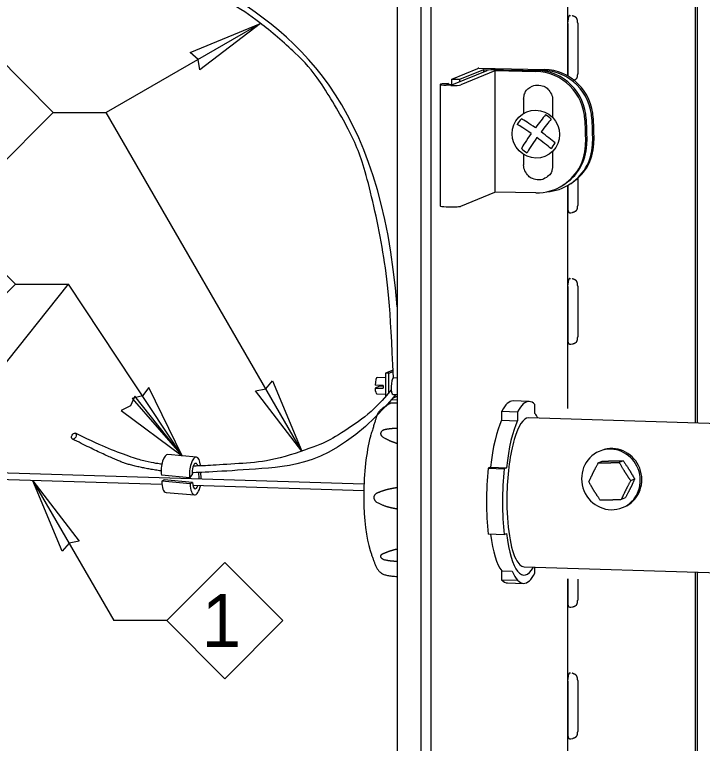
# Model space of a CAD drawing. Extents: x 99862 to 104211, y 98939 to 102076.
# Drawn here: x 102537.9 to 102745.8, y 100948.7 to 101168.9 of the extents above; entities that cross this region are included whole.
import ezdxf

# ---------------------------------------------------------------- set-up
doc = ezdxf.new("R2010")
doc.units = 0
for name, color, linetype in [('Level 1', 7, 'Continuous'), ('Level 11', 7, 'Continuous'), ('Level 15', 7, 'Continuous'), ('Level 16', 7, 'Continuous'), ('Level 18', 7, 'Continuous'), ('Level 19', 7, 'Continuous'), ('Level 20', 7, 'Continuous'), ('Level 22', 7, 'Continuous'), ('Level 30', 7, 'Continuous'), ('Level 4', 7, 'Continuous'), ('Level 5', 7, 'Continuous'), ('Level 6', 7, 'Continuous'), ('Level 8', 7, 'Continuous'), ('Level 9', 7, 'Continuous')]:
    doc.layers.add(name, color=color, linetype=linetype)

msp = doc.modelspace()

# ---------------------------------------------------------------- linework, layer by layer
at = {"layer": 'Level 1'}
for p, q in [((102705.04, 101245.44), (102705.04, 101150.38)), ((102660.74, 101228.18), (102660.74, 100794.54)), ((102663.81, 100794.74), (102663.81, 101228.38)), ((102653.5, 101220.95), (102653.5, 100802.46)), ((102705.04, 101117.28), (102705.04, 101049.91)), ((102705.13, 101049.91), (102705.13, 101070.65)), ((102705.04, 100998.38), (102705.04, 100905.03))]:
    msp.add_line(p, q, dxfattribs=at)
at = {"layer": 'Level 11'}
msp.add_ellipse((102695.46, 101132.81), major_axis=(-4.03, 6.06), ratio=0.979824, dxfattribs=at)
for centre, major_axis, ratio, start_param, end_param in [((102695.55, 101132.92), (-5.39, -3.58), 0.979824, 4.901469, 5.233429), ((102696.66, 101133.08), (6.17, -4.54), 0.069723, 1.843795, 2.744743), ((102695.44, 101134.01), (4.54, 6.17), 0.069723, 0.774623, 1.506857), ((102697.16, 101132.74), (-4.54, -6.17), 0.069723, 3.916018, 4.645885), ((102695.6, 101132.9), (3.58, -5.39), 0.979824, 1.762443, 2.094403), ((102695.39, 101131.36), (-6.17, 4.54), 0.069723, 4.983765, 5.886534), ((102695.44, 101134.01), (4.54, 6.17), 0.069723, 1.787106, 2.744743), ((102696.66, 101133.08), (6.17, -4.54), 0.069723, 0.774623, 1.561852), ((102697.16, 101132.74), (-4.54, -6.17), 0.069723, 4.926025, 5.886534), ((102695.39, 101131.36), (-6.17, 4.54), 0.069723, 3.916018, 4.702017), ((102695.55, 101132.92), (-5.39, -3.58), 0.979824, 1.762443, 2.094403), ((102695.6, 101132.9), (3.58, -5.39), 0.979824, 4.901469, 5.233429)]:
    msp.add_ellipse(centre, major_axis=major_axis, ratio=ratio, start_param=start_param, end_param=end_param, dxfattribs=at)
at = {"layer": 'Level 15'}
for p, q in [((102612.19, 101166.29), (102565.57, 101139.38)), ((102549.57, 101139.38), (102565.57, 101139.38)), ((102624.71, 101036.95), (102565.57, 101139.38)), ((102514.53, 101037.79), (102554.21, 101087.44)), ((102538.21, 101087.44), (102554.21, 101087.44)), ((102588.56, 101035.57), (102554.21, 101087.44)), ((102543.46, 101028.07), (102567.88, 100985.78)), ((102583.88, 100985.78), (102567.88, 100985.78))]:
    msp.add_line(p, q, dxfattribs=at)
for points in [[(102612.19, 101166.29), (102593.92, 101152.29), (102593.34, 101155.41), (102590.93, 101157.46)], [(102624.71, 101036.95), (102610.71, 101055.23), (102613.82, 101055.81), (102615.88, 101058.22)], [(102588.56, 101035.57), (102578.44, 101056.25), (102576.54, 101053.72), (102573.46, 101052.96)], [(102588.56, 101035.57), (102574.25, 101053.61), (102572.93, 101050.73), (102570.09, 101049.32)], [(102543.46, 101028.07), (102557.46, 101009.79), (102554.35, 101009.21), (102552.29, 101006.8)]]:
    msp.add_lwpolyline(points, close=True, dxfattribs=at)
at = {"layer": 'Level 16'}
for p, q in [((102592.85, 101035.17), (102584.26, 101035.97)), ((102594.12, 101032.54), (102594.1, 101032.72)), ((102590.86, 101028.94), (102582.27, 101029.73)), ((102590.86, 101028.94), (102591.58, 101029.85)), ((102593.46, 101030.52), (102593.57, 101028.75)), ((102594.34, 101028.79), (102594.23, 101030.54)), ((102583.13, 101028.31), (102582.38, 101027.94)), ((102590.96, 101027.15), (102582.38, 101027.94)), ((102591.72, 101027.52), (102583.13, 101028.31)), ((102591.72, 101027.52), (102590.96, 101027.15)), ((102583.68, 101024.55), (102592.26, 101023.76))]:
    msp.add_line(p, q, dxfattribs=at)
for centre, major_axis, start_param, end_param in [((102583.88, 101031.76), (0.39, 4.21), 0, 2.107327), ((102592.46, 101030.96), (0.39, 4.21), 0, 2.107327), ((102592.46, 101030.96), (0.39, 4.21), 5.178942, 6.283185), ((102592.46, 101030.96), (-0.21, -2.33), 3.141593, 5.248919), ((102592.46, 101030.96), (-0.21, -2.33), 2.333431, 3.141593), ((102592.65, 101027.97), (-0.21, -2.33), 1.854796, 1.949891), ((102592.65, 101027.97), (0.39, 4.21), 4.8789, 4.944488), ((102584.06, 101028.76), (0.39, 4.21), 1.802895, 3.141593), ((102592.65, 101027.97), (0.39, 4.21), 1.802895, 3.141593), ((102592.65, 101027.97), (-0.21, -2.33), 4.944488, 6.283185), ((102592.65, 101027.97), (0.39, 4.21), 3.141593, 4.398099), ((102592.65, 101027.97), (-0.21, -2.33), 0, 0.950425)]:
    msp.add_ellipse(centre, major_axis=major_axis, ratio=0.389923, start_param=start_param, end_param=end_param, dxfattribs=at)
at = {"layer": 'Level 18'}
for p, q in [((102744.31, 101045.46), (102744.31, 101252.37)), ((102743.65, 101000.46), (102743.65, 100805.07))]:
    msp.add_line(p, q, dxfattribs=at)
for points in [[(102685.75, 101253.86), (102686.4, 101254.13), (102744.31, 101252.37), (102743.65, 101252.1), (102743.65, 101045.48)], [(102696.2, 100806.51), (102743.65, 100805.07), (102744.31, 100805.34), (102744.31, 101000.44)]]:
    msp.add_lwpolyline(points, dxfattribs=at)
at = {"layer": 'Level 19'}
for p, q in [((102715.12, 101037.13), (102714.63, 101036.93)), ((102714.32, 101033.44), (102715.54, 101033.94)), ((102721.86, 101034.12), (102720.63, 101033.61)), ((102725.32, 101028.57), (102724.1, 101028.06)), ((102722.47, 101022.84), (102721.25, 101022.34)), ((102721.66, 101019.94), (102722.15, 101020.14))]:
    msp.add_line(p, q, dxfattribs=at)
for centre, start_param, end_param in [((102718.15, 101028.44), 2.914664, 3.141593), ((102718.63, 101028.64), 2.914664, 3.141593), ((102718.15, 101028.44), 6.283185, 9.197849), ((102718.63, 101028.64), 6.283185, 9.197849), ((102718.15, 101028.44), 3.141593, 6.283185)]:
    msp.add_ellipse(centre, major_axis=(3.52, -8.5), ratio=0.959029, start_param=start_param, end_param=end_param, dxfattribs=at)
for points in [[(102711.47, 101027.71), (102712.34, 101029.59), (102713.28, 101031.49), (102714.32, 101033.44)], [(102714.32, 101033.44), (102716.34, 101033.46), (102718.44, 101033.52), (102720.63, 101033.61)], [(102715.54, 101033.94), (102717.73, 101034.04), (102719.84, 101034.1), (102721.86, 101034.12)], [(102720.63, 101033.61), (102721.96, 101031.32), (102723, 101029.68), (102724.1, 101028.06)], [(102721.86, 101034.12), (102723.35, 101031.9), (102724.37, 101030.25), (102725.32, 101028.57)], [(102725.32, 101028.57), (102724.46, 101026.7), (102723.51, 101024.79), (102722.47, 101022.84)], [(102714.94, 101022.16), (102713.69, 101023.97), (102712.55, 101025.83), (102711.47, 101027.71)], [(102724.1, 101028.06), (102723.07, 101026.12), (102722.11, 101024.21), (102721.25, 101022.34)], [(102721.25, 101022.34), (102719.06, 101022.24), (102716.96, 101022.18), (102714.94, 101022.16)]]:
    msp.add_open_spline(points, degree=2, dxfattribs=at)
at = {"layer": 'Level 20'}
for points in [[(102532.02, 101156.93), (102549.57, 101139.38), (102532.02, 101121.82), (102514.47, 101139.38)], [(102520.66, 101104.99), (102538.21, 101087.44), (102520.66, 101069.89), (102503.1, 101087.44)], [(102601.43, 101003.33), (102618.99, 100985.78), (102601.43, 100968.22), (102583.88, 100985.78)]]:
    msp.add_lwpolyline(points, close=True, dxfattribs=at)
at = {"layer": 'Level 22'}
for p, q in [((102705.72, 101168.7), (102705.7, 101168.7)), ((102705.72, 101168.7), (102705.87, 101168.69)), ((102705.1, 101166.21), (102705.1, 101150.82)), ((102708.1, 101166.38), (102708.1, 101151)), ((102708.1, 101119.45), (102708.1, 101111.25)), ((102705.1, 101117.31), (102705.1, 101111.08)), ((102705.63, 101109.06), (102705.84, 101109.06)), ((102705.72, 101089.2), (102705.7, 101089.21)), ((102705.72, 101089.2), (102705.87, 101089.2)), ((102705.1, 101086.71), (102705.1, 101071.33)), ((102708.1, 101086.89), (102708.1, 101071.5)), ((102705.63, 101069.32), (102705.84, 101069.31)), ((102705.1, 100998.38), (102705.1, 100991.84)), ((102708.1, 100998.29), (102708.1, 100992.01)), ((102705.63, 100989.82), (102705.84, 100989.82)), ((102705.72, 100969.96), (102705.7, 100969.96)), ((102705.72, 100969.96), (102705.87, 100969.96)), ((102705.1, 100967.47), (102705.1, 100952.09)), ((102708.1, 100967.64), (102708.1, 100952.26)), ((102705.63, 100950.07), (102705.84, 100950.07))]:
    msp.add_line(p, q, dxfattribs=at)
for points in [[(102705.84, 101109.06), (102706.03, 101109.06), (102706.54, 101109.17)], [(102705.84, 101069.31), (102706.03, 101069.32), (102706.54, 101069.42)], [(102705.84, 100989.82), (102706.03, 100989.82), (102706.54, 100989.93)], [(102705.84, 100950.07), (102706.03, 100950.08), (102706.54, 100950.18)]]:
    msp.add_lwpolyline(points, dxfattribs=at)
for centre in [(102705.83, 101168.71), (102705.83, 101089.21), (102705.83, 100969.97)]:
    msp.add_ellipse(centre, major_axis=(0.129, 0), ratio=0.112235, start_param=3.805799, end_param=5.089246, dxfattribs=at)
for points in [[(102705.7, 101168.7), (102705.4, 101168.53), (102705.21, 101167.87), (102705.12, 101166.75)], [(102708.1, 101166.38), (102708.04, 101167.53), (102707.47, 101168.28), (102706.4, 101168.62)], [(102705.1, 101150.82), (102705.1, 101150.65), (102705.11, 101150.49), (102705.12, 101150.34)], [(102706.98, 101149.08), (102707.69, 101149.46), (102708.07, 101150.09), (102708.1, 101151)], [(102705.1, 101111.08), (102705.12, 101109.94), (102705.27, 101109.27), (102705.56, 101109.08)], [(102706.56, 101109.15), (102707.54, 101109.49), (102708.06, 101110.18), (102708.1, 101111.25)], [(102705.7, 101089.21), (102705.4, 101089.04), (102705.21, 101088.38), (102705.12, 101087.26)], [(102708.1, 101086.89), (102708.04, 101088.03), (102707.47, 101088.78), (102706.4, 101089.13)], [(102705.1, 101071.33), (102705.12, 101070.19), (102705.27, 101069.52), (102705.56, 101069.33)], [(102706.56, 101069.4), (102707.54, 101069.74), (102708.06, 101070.43), (102708.1, 101071.5)], [(102705.1, 100991.84), (102705.12, 100990.7), (102705.27, 100990.03), (102705.56, 100989.84)], [(102706.56, 100989.91), (102707.54, 100990.25), (102708.06, 100990.94), (102708.1, 100992.01)], [(102705.7, 100969.96), (102705.4, 100969.79), (102705.21, 100969.14), (102705.12, 100968.02)], [(102708.1, 100967.64), (102708.04, 100968.79), (102707.47, 100969.54), (102706.4, 100969.89)], [(102705.1, 100952.09), (102705.12, 100950.95), (102705.27, 100950.28), (102705.56, 100950.09)], [(102706.56, 100950.16), (102707.54, 100950.5), (102708.06, 100951.19), (102708.1, 100952.26)]]:
    msp.add_open_spline(points, degree=2, dxfattribs=at)
at = {"layer": 'Level 30'}
for p, q in [((102643.49, 101027.02), (102477.02, 101032.09)), ((102582.44, 101026.88), (102517.77, 101028.85)), ((102643.43, 101025.02), (102591.81, 101026.59))]:
    msp.add_line(p, q, dxfattribs=at)
msp.add_ellipse((102555.82, 101041.55), major_axis=(0.447, 0.894), ratio=0.626669, dxfattribs=at)
for points, degree in [([(102652.41, 101059.13), (102651.5, 101080.89), (102649.81, 101096.71), (102643.91, 101122.9), (102639.7, 101133.26), (102629.63, 101150.15), (102623.77, 101156.69), (102611.07, 101167.56), (102604.24, 101171.89), (102583.43, 101183.84), (102569.35, 101190.28), (102544.15, 101200.52), (102533.03, 101204.31), (102517.07, 101209.68), (102512.28, 101211.24), (102507.45, 101212.64), (102506.24, 101212.95), (102504.21, 101213.38), (102503.39, 101213.51), (102502.46, 101213.62), (102502.41, 101213.63), (102502.36, 101213.63)], 3), ([(102653.5, 101080.61), (102648.82, 101143.1), (102596.56, 101184.64), (102512.98, 101213.37), (102506.37, 101215.18), (102502.55, 101215.62), (102502.45, 101215.64)], 3), ([(102651.75, 101055.51), (102647.59, 101050.55), (102643.2, 101046.72), (102634.21, 101040.74), (102629.6, 101038.61), (102615.95, 101033.99), (102607.08, 101033.3), (102596.88, 101032.66), (102594.32, 101032.52), (102591.89, 101032.48)], 3), ([(102653.18, 101054.11), (102635.91, 101033.6), (102610.25, 101031.39), (102594.13, 101030.5), (102591.53, 101030.47)], 3), ([(102582.4, 101033.02), (102581.76, 101033.11), (102581.12, 101033.22), (102577.31, 101033.93), (102573.93, 101034.87), (102566.07, 101037.8), (102561.6, 101039.78), (102556.27, 101042.45)], 3), ([(102582.19, 101031.03), (102575.08, 101032.05), (102567.27, 101034.71), (102555.38, 101040.66)], 2)]:
    msp.add_open_spline(points, degree=degree, dxfattribs=at)
at = {"layer": 'Level 4'}
for p, q in [((102693.4, 101052.02), (102688.58, 101052.16)), ((102695.18, 101048.38), (102695.18, 101051.07)), ((102685.12, 101049.05), (102689.95, 101048.9)), ((102685.12, 101049.05), (102685.12, 101046.36)), ((102689.95, 101048.9), (102689.95, 101046.21)), ((102685.12, 101046.36), (102689.95, 101046.21)), ((102780.74, 101044.35), (102693.25, 101047.02)), ((102681.74, 101032.13), (102681.03, 101031.84)), ((102681.03, 101031.84), (102685.86, 101031.69)), ((102681.74, 101032.13), (102686.57, 101031.98)), ((102686.57, 101031.98), (102685.86, 101031.69)), ((102681.03, 101011.96), (102685.86, 101011.82)), ((102685.86, 101011.82), (102686.57, 101012.11)), ((102685.12, 101000.82), (102685.12, 100998.14)), ((102685.12, 101000.82), (102688.31, 101000.73)), ((102691.88, 101002.04), (102779.37, 100999.37)), ((102695.18, 101000.16), (102695.18, 101001.94)), ((102685.12, 100998.14), (102689.95, 100997.99)), ((102686.9, 100997.19), (102691.73, 100997.04))]:
    msp.add_line(p, q, dxfattribs=at)
for centre, major_axis, start_param, end_param in [((102687.74, 101024.67), (0.84, 27.49), 0, 0.488668), ((102692.57, 101024.53), (0.84, 27.49), 0, 0.488668), ((102692.57, 101024.53), (0.84, 27.49), 6.027517, 6.283185), ((102687.74, 101024.67), (0.76, 24.99), 0.528017, 1.275779), ((102692.57, 101024.53), (0.76, 24.99), 0.528017, 1.275779), ((102692.57, 101024.53), (-0.68, -22.49), 3.141593, 4.720308), ((102692.57, 101024.53), (0.76, 24.99), 5.832158, 5.988168), ((102687.74, 101024.67), (0.84, 27.49), 1.315128, 2.059465), ((102692.57, 101024.53), (0.84, 27.49), 1.315128, 2.059465), ((102692.57, 101024.53), (-0.68, -22.49), 4.720308, 5.826995), ((102687.74, 101024.67), (0.76, 24.99), 2.113433, 2.846576), ((102692.57, 101024.53), (0.76, 24.99), 2.098813, 3.592619), ((102692.57, 101024.53), (-0.68, -22.49), 5.826995, 6.283185), ((102692.57, 101024.53), (0.84, 27.49), 2.625625, 3.141593), ((102692.57, 101024.53), (0.84, 27.49), 3.141593, 3.630261), ((102687.74, 101024.67), (0.84, 27.49), 2.885924, 3.141593)]:
    msp.add_ellipse(centre, major_axis=major_axis, ratio=0.260126, start_param=start_param, end_param=end_param, dxfattribs=at)
at = {"layer": 'Level 5'}
for start_param, end_param in [(4.043491, 5.65979), (4.007567, 4.043491), (3.977635, 4.007567)]:
    msp.add_ellipse((102649.54, 101025.84), major_axis=(-0.71, -23.39), ratio=0.260126, start_param=start_param, end_param=end_param, dxfattribs=at)
for points in [[(102651.6, 101051.45), (102647.96, 101049.63), (102646.81, 101045.85), (102645.48, 101041.58)], [(102650.24, 101043.57), (102649.01, 101043.4), (102648.29, 101042.04), (102649.07, 101041.35)], [(102653.5, 101043.88), (102652.41, 101043.83), (102651.32, 101043.74), (102650.24, 101043.57)], [(102649.07, 101041.35), (102650.87, 101040.34), (102652.17, 101039.82), (102653.5, 101039.36)], [(102647.9, 101024.48), (102646.72, 101024.11), (102646.32, 101022.44), (102647.26, 101021.57)], [(102653.5, 101025.94), (102651.59, 101025.62), (102649.7, 101025.2), (102647.9, 101024.48)], [(102647.26, 101021.57), (102649.72, 101020.44), (102651.6, 101019.94), (102653.5, 101019.56)], [(102645.41, 101006.95), (102646.53, 101003.24), (102648.83, 100999.2), (102653.5, 100999.15)], [(102653.5, 101007.38), (102652.16, 101007.02), (102650.84, 101006.61), (102649.62, 101006.1)], [(102649.62, 101006.1), (102648.53, 101005.75), (102648.44, 101004.76), (102649.53, 101004.21)], [(102649.53, 101004.21), (102651.32, 101003.87), (102652.41, 101003.8), (102653.5, 101003.75)]]:
    msp.add_open_spline(points, degree=2, dxfattribs=at)
at = {"layer": 'Level 6'}
for p, q in [((102670.11, 101149.46), (102677.91, 101152.69)), ((102672.52, 101149.38), (102679.72, 101152.36)), ((102678.19, 101152.71), (102697.97, 101152.33)), ((102679.72, 101152.36), (102679.72, 101151.65)), ((102679.73, 101152.37), (102679.76, 101152.39)), ((102679.73, 101151.65), (102679.73, 101152.37)), ((102679.76, 101152.39), (102697.56, 101152.05)), ((102679.76, 101152.39), (102679.76, 101151.67)), ((102670.11, 101149.46), (102672.52, 101149.38)), ((102670.11, 101147.79), (102670.11, 101149.46)), ((102672.52, 101148.67), (102672.52, 101149.38)), ((102712.34, 101137.33), (102712.55, 101130.6)), ((102712.76, 101137.61), (102712.97, 101130.87)), ((102705.86, 101117.78), (102706.28, 101118.06))]:
    msp.add_line(p, q, dxfattribs=at)
for centre, major_axis, ratio, start_param, end_param in [((102678.15, 101152.68), (0.25, 0), 0.112235, 1.403591, 2.876726), ((102679.48, 101152.37), (0.25, 0), 0.112235, 5.949784, 6.11598), ((102697.56, 101137.15), (-8.31, 12.49), 0.979824, 4.147244, 5.686921), ((102697.97, 101137.43), (-8.31, 12.49), 0.979824, 4.14725, 5.686921), ((102697.77, 101130.41), (-8.31, 12.49), 0.979824, 3.141593, 4.147252), ((102698.18, 101130.69), (-8.31, 12.49), 0.979824, 3.141593, 4.147252), ((102697.56, 101130.27), (-8.31, 12.49), 0.979824, 2.628874, 3.141593)]:
    msp.add_ellipse(centre, major_axis=major_axis, ratio=ratio, start_param=start_param, end_param=end_param, dxfattribs=at)
at = {"layer": 'Level 8'}
for p, q in [((102652.3, 101061.51), (102650.06, 101060.58)), ((102650.06, 101060.58), (102650.06, 101053.57)), ((102651.06, 101060.55), (102650.06, 101060.58)), ((102651.06, 101060.55), (102652.32, 101061.08)), ((102651.06, 101054.7), (102651.06, 101060.55)), ((102650.06, 101059.2), (102647.59, 101059.28)), ((102653.5, 101059.1), (102652.44, 101059.13)), ((102649.28, 101056.88), (102646.87, 101056.95)), ((102648.16, 101056.61), (102646.87, 101056.08)), ((102646.87, 101056.08), (102649.28, 101056)), ((102649.27, 101056.57), (102648.16, 101056.61)), ((102647.44, 101054.28), (102650.06, 101054.2)), ((102653.5, 101053.53), (102652.24, 101053.01)), ((102652.29, 101054.13), (102653.5, 101054.1)), ((102651, 101051.63), (102653.5, 101051.55)), ((102653.5, 101052.45), (102651.79, 101052.5))]:
    msp.add_line(p, q, dxfattribs=at)
for centre, start_param, end_param in [((102647.51, 101056.78), 0, 1.509989), ((102652.37, 101056.63), 0.1165, 3.141593), ((102652.37, 101056.63), 0, 0.1165), ((102647.51, 101056.78), 1.864603, 3.141593), ((102649.92, 101056.71), 1.509989, 1.864603)]:
    msp.add_ellipse(centre, major_axis=(0.08, 2.5), ratio=0.260126, start_param=start_param, end_param=end_param, dxfattribs=at)
at = {"layer": 'Level 9'}
for p, q in [((102670.57, 101147.86), (102680.74, 101152.07)), ((102683.08, 101151.97), (102672.81, 101147.72)), ((102683.09, 101151.97), (102683.08, 101151.97)), ((102683.09, 101151.97), (102683.13, 101152)), ((102683.09, 101152), (102683.09, 101116.48)), ((102683.13, 101152), (102695.46, 101151.76)), ((102683.57, 101152.27), (102695.87, 101152.04)), ((102666.54, 101147.83), (102666.54, 101111.14)), ((102666.63, 101147.9), (102667.21, 101148.14)), ((102667.21, 101148.14), (102669.03, 101148.09)), ((102669.74, 101147.52), (102668.39, 101147.56)), ((102669.03, 101148.09), (102668.62, 101147.92)), ((102668.62, 101147.92), (102668.62, 101147.86)), ((102669.03, 101148.09), (102669.03, 101147.8)), ((102669.33, 101147.78), (102669.34, 101147.78)), ((102683.08, 101146.3), (102683.08, 101115.28)), ((102691.77, 101143.35), (102691.77, 101139.08)), ((102700.53, 101143.06), (102700.52, 101137.84)), ((102710.24, 101137.04), (102710.45, 101130.3)), ((102710.66, 101137.32), (102710.86, 101130.58)), ((102691.77, 101126.67), (102691.77, 101123.57)), ((102700.48, 101127.55), (102700.47, 101122.53)), ((102703.76, 101117.49), (102704.18, 101117.77)), ((102672.81, 101111.03), (102683.08, 101115.28)), ((102683.08, 101115.28), (102683.09, 101115.28)), ((102683.13, 101115.31), (102683.09, 101115.28)), ((102695.46, 101115.08), (102683.13, 101115.31)), ((102668.39, 101110.87), (102669.74, 101110.83))]:
    msp.add_line(p, q, dxfattribs=at)
for centre, major_axis, ratio, start_param, end_param in [((102683.15, 101152), (-2.5, 0), 0.112235, 4.545184, 6.018319), ((102695.87, 101137.13), (-8.31, 12.49), 0.979824, 4.147247, 5.686921), ((102695.46, 101136.86), (-8.31, 12.49), 0.979824, 4.147247, 5.686921), ((102669.04, 101147.83), (-2.5, 0), 0.112235, 6.018319, 6.283185), ((102669.04, 101147.83), (-2.5, 0), 0.112235, 6.283185, 7.589115), ((102669.59, 101147.89), (1, 0), 0.112235, 2.876726, 3.141593), ((102669.59, 101147.89), (1, 0), 0.112235, 3.141593, 4.447522), ((102669.6, 101147.89), (1, 0), 0.112235, 4.447522, 6.018319), ((102670.4, 101147.79), (-2.5, 0), 0.112235, 1.30593, 2.876726), ((102695.66, 101130.12), (-8.31, 12.49), 0.979824, 3.141593, 4.147254), ((102696.08, 101130.4), (-8.31, 12.49), 0.979824, 3.141593, 4.14725), ((102695.46, 101129.98), (-8.31, 12.49), 0.979824, 2.545328, 3.141593), ((102669.04, 101111.14), (2.5, 0), 0.112235, 3.141593, 4.447522), ((102670.4, 101111.1), (2.5, 0), 0.112235, 4.447522, 6.018319)]:
    msp.add_ellipse(centre, major_axis=major_axis, ratio=ratio, start_param=start_param, end_param=end_param, dxfattribs=at)
for points in [[(102693.67, 101146.94), (102694.62, 101147.57), (102695.78, 101147.79), (102698.07, 101147.31), (102699.09, 101146.61), (102700.27, 101144.84), (102700.54, 101143.95), (102700.53, 101143.06)], [(102691.77, 101143.35), (102691.77, 101143.63), (102691.8, 101143.9), (102692.07, 101145.33), (102692.72, 101146.31), (102693.67, 101146.94)], [(102700.47, 101122.53), (102700.46, 101122.51), (102700.46, 101122.48), (102700.23, 101121.31), (102699.58, 101120.33), (102697.69, 101119.07), (102696.53, 101118.85), (102694.24, 101119.33), (102693.21, 101120.03), (102692.03, 101121.8), (102691.77, 101122.68), (102691.77, 101123.57)]]:
    msp.add_open_spline(points, degree=3, dxfattribs=at)

# ---------------------------------------------------------------- texts
at = {"layer": 'Level 20'}
msp.add_text('1', height=16, dxfattribs=at).set_placement((102594.48, 100977.78))

doc.saveas('drawing.dxf')
